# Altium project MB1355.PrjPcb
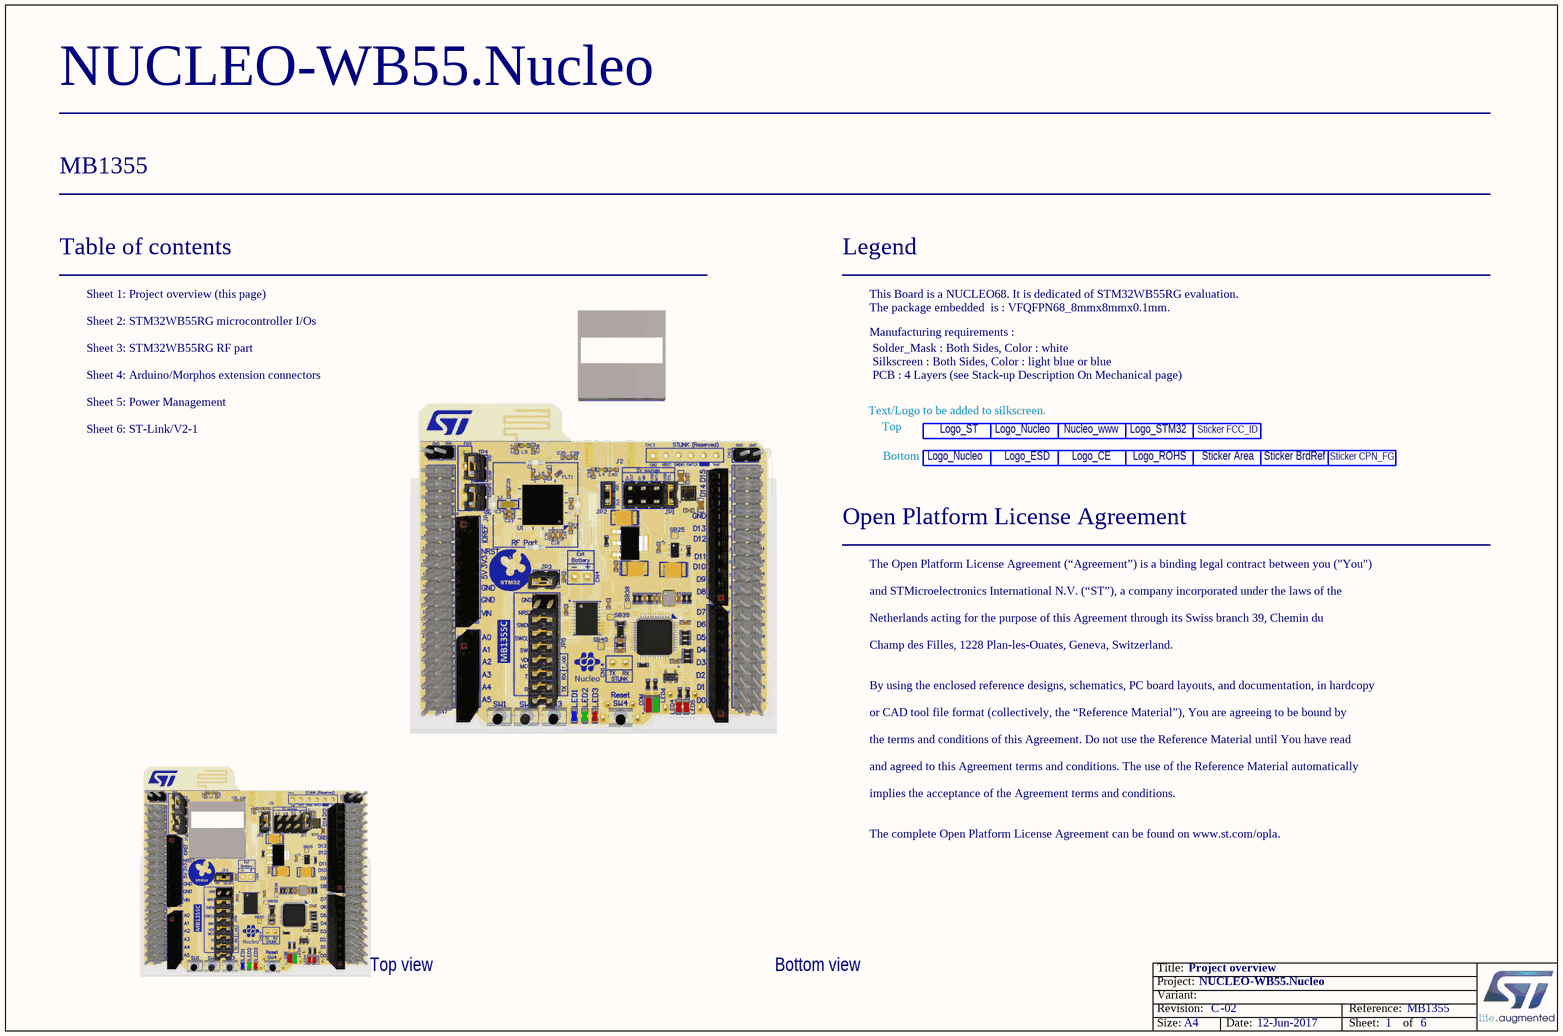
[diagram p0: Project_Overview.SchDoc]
Board_Reference: MB1355; Board_PCB_Revision: C; Board_Name: NUCLEO-WB55.Nucleo; Board_Document_Date: 12-Jun-2017; Board_Assembly_Revision: 02
6 sheets, 214 parts. Net scope: flat (ports and power ports of the same name join across sheets).
Board file: MB1355.PcbDoc
Sheets:
  Project_Overview.SchDoc
  MCU.SchDoc
  RF.SchDoc
  Extension_CN.SchDoc
  ST_LINK_V2-1.SCHDOC
  Power_Management.SchDoc

## Sheet Project_Overview.SchDoc: Project overview
size A4; Date: Not used; ApprovedBy: Not used; CheckedBy: Not used; Author: Ph.A; CompanyName: STMicroelectronics; DrawnBy: Not used; Engineer: Not used; Organization: Not used; Address1: Not used; Address2: Not used; Address3: Not used; Address4: Not used; DocumentNumber: Not used; Revision: Not used; SheetNumber: 1; SheetTotal: 6

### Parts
Label_1  LOGO_ST  [LOGO_ST_Size3]  (value not drawn)
Label_2  LOGO_ROHS  [SYMBOL_RoHS]  (value not drawn)
Label_3  LOGO_Nucleo_www  [LOGO_Nucleo_www]  (value not drawn)
Label_4  LOGO_STM32  [LOGO_STM32]  (value not drawn)
Label_5  LOGO_Nucleo  [LOGO_Nucleo]  (value not drawn)
Label_6  LOGO_CE  [LOGO CE]  (value not drawn)
Label_7  LOGO_ESD  [LOGO ESD]  (value not drawn)
Label_8  LOGO_StickerArea_W21x6  [LOGO_StickerArea_Border]  (value not drawn)
Label_9  LOGO_Nucleo  [LOGO_Nucleo]  (value not drawn)
STICKER_1  FCC_ID_Sticker_16x5  [Sticker_FCC_ID 16x5mm]  (value not drawn)
STICKER_2  Sticker_BrdRef_21x5  [Sticker_BrdRef_21x5mm]  (value not drawn)
STICKER_3  Sticker_CPN_FG 16x5  [Sticker_CPN_FG 16x5mm]  (value not drawn)

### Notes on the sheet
- Table of contents
- Sheet 1: Project overview (this page)
- Legend
- This Board is a NUCLEO68. It is dedicated of STM32WB55RG evaluation.
- The package embedded  is : VFQFPN68_8mmx8mmx0.1mm.
- Sheet 2: STM32WB55RG microcontroller I/Os
- Sheet 3: STM32WB55RG RF part
- Sheet 4: Arduino/Morphos extension connectors
- Manufacturing requirements :
- Silkscreen : Both Sides, Color : light blue or blue
- Solder_Mask : Both Sides, Color : white
- PCB : 4 Layers (see Stack-up Description On Mechanical page)
- Sheet 6: ST-Link/V2-1
- Sheet 5: Power Management
- Text/Logo to be added to silkscreen.
- Top
- Bottom
- Open Platform License Agreement
- The Open Platform License Agreement (“Agreement”) is a binding legal contract between you ("You")
- and STMicroelectronics International N.V. (“ST”), a company incorporated under the laws of the
- Netherlands acting for the purpose of this Agreement through its Swiss branch 39, Chemin du
- Champ des Filles, 1228 Plan-les-Ouates, Geneva, Switzerland.
- By using the enclosed reference designs, schematics, PC board layouts, and documentation, in hardcopy
- or CAD tool file format (collectively, the “Reference Material”), You are agreeing to be bound by
- the terms and conditions of this Agreement. Do not use the Reference Material until You have read
- and agreed to this Agreement terms and conditions. The use of the Reference Material automatically
- implies the acceptance of the Agreement terms and conditions.
- The complete Open Platform License Agreement can be found on www.st.com/opla.
- Top view
- Bottom view

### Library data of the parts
Label_1 = LOGO_ST: Silkscreen Only: YES
Label_2 = LOGO_ROHS: Silkscreen Only: YES
Label_4 = LOGO_STM32: Silkscreen Only: YES
Label_5 Label_9 = LOGO_Nucleo: Silkscreen Only: YES
Label_6 = LOGO_CE: Silkscreen Only: YES
Label_7 = LOGO_ESD: Silkscreen Only: YES
Label_8 = LOGO_StickerArea_W21x6: Silkscreen Only: YES
STICKER_1 = LOGO_Sticker_FCC_ID: Sticker for FCC_ID 16x5mm
STICKER_2 = LOGO_Sticker_BrdRef: Sticker_BrdRef 21x5mm
STICKER_3 = LOGO_Sticker_CPN_FG: Sticker for CPN_FG 16x5mm

## Sheet MCU.SchDoc: STM32WB55RG microcontroller I/Os
size A4; Author: Ph.A; SheetNumber: 2; SheetTotal: 6
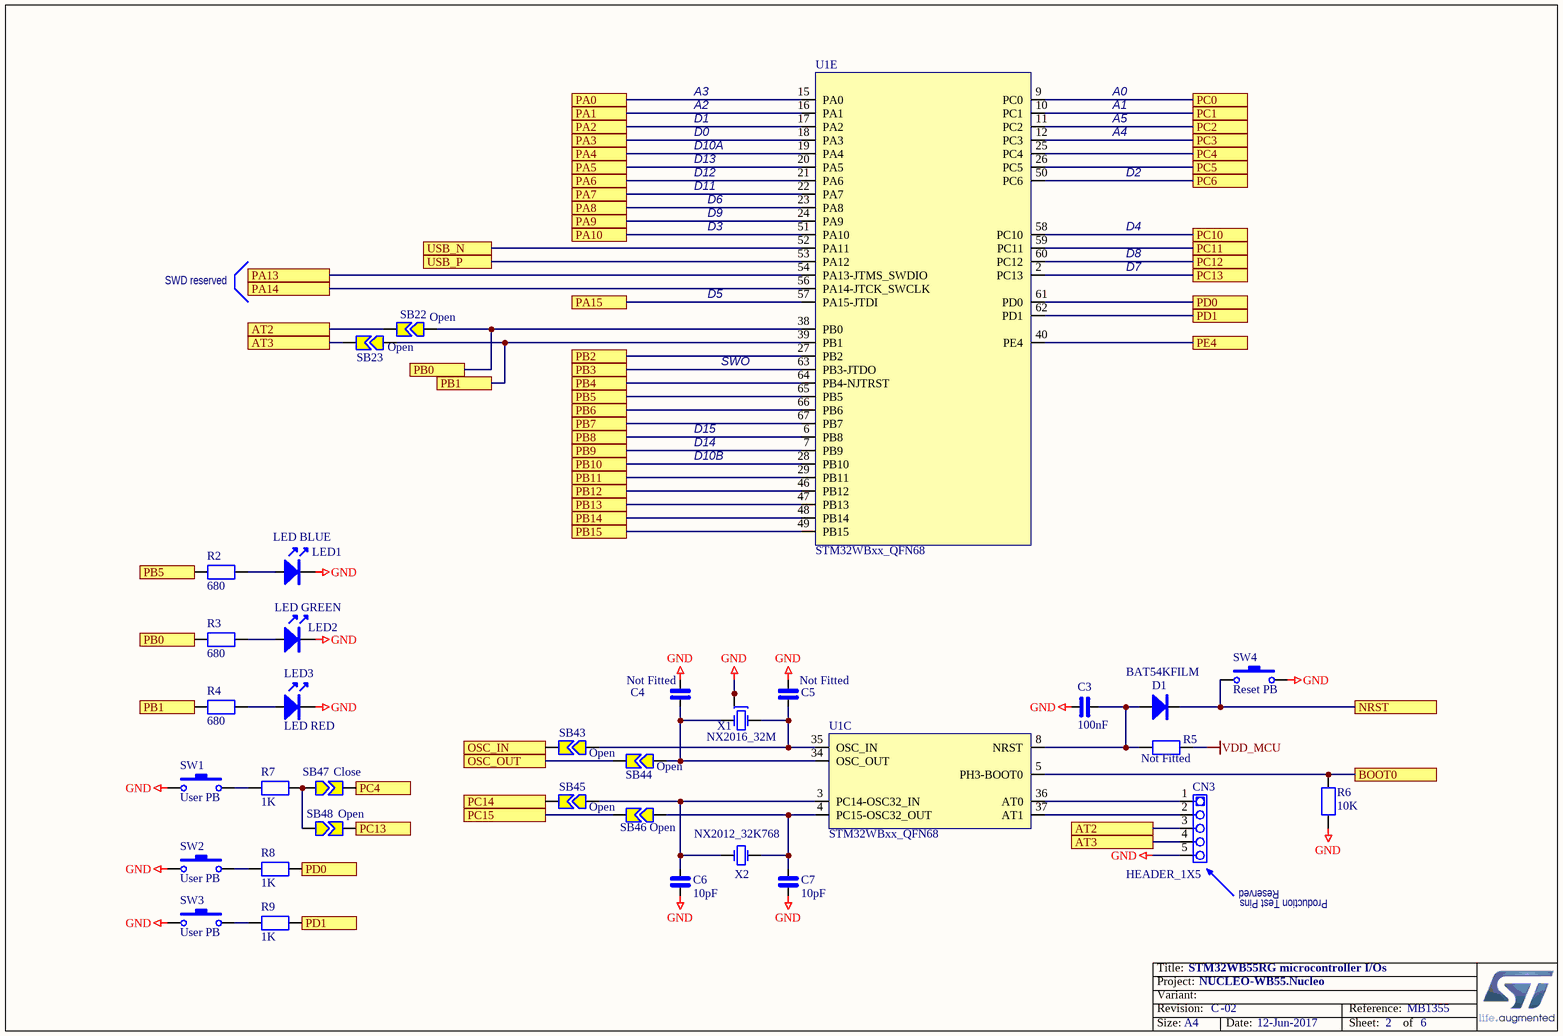
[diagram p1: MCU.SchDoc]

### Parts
C3  100nF  [0402_CAP_NPOL]
C4  Fitted: Not Fitted  [0402_CAP_NPOL]  (hidden comment: TBD)
C5  Fitted: Not Fitted  [0402_CAP_NPOL]  (hidden comment: TBD)
C6  10pF  [0402_CAP_NPOL]
C7  10pF  [0402_CAP_NPOL]
CN3  HEADER_1X5  [Header NF 1x5x2.54 TH]
D1  BAT54KFILM  [SOD523]
LED1  LED BLUE  [0603_LED_Blue]
LED2  LED GREEN  [0603_LED_GREEN]
LED3  LED RED  [0603_LED_RED]
R2  680  [0402_RES]
R3  680  [0402_RES]
R4  680  [0402_RES]
R5  Fitted: Not Fitted  [0402_RES]  (hidden comment: 100K (not fitted))
R6  10K  [0402_RES]
R7  1K  [0402_RES]
R8  1K  [0402_RES]
R9  1K  [0402_RES]
SB22  Open  [SB-tiny]
SB23  Open  [SB-tiny]
SB43  Open  [SB-tiny]
SB44  Open  [SB-tiny]
SB45  Open  [SB-tiny]
SB46  Open  [SB-tiny]
SB47  Close  [SB-tiny]
SB48  Open  [SB-tiny]
SW1  User PB  [SW-PB SMD KMR2]
SW2  User PB  [SW-PB SMD KMR2]
SW3  User PB  [SW-PB SMD KMR2]
SW4  Reset PB  [SW-PB SMD KMR2]
U1  STM32WBxx_QFN68  [VFQFPN68_8x8x0.1_p0.4]  (parts C,E of 5)
X1  NX2016_32M  [NX2016_4P]
X2  NX2012_32K768  [NX2012_2P]

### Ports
AT2, AT3, BOOT0, NRST, OSC_IN, OSC_OUT, PA0, PA1, PA2, PA3, PA4, PA5, PA6, PA7, PA8, PA9, PA10, PA13, PA14, PA15, PB0, PB1, PB2, PB3, PB4, PB5, PB6, PB7, PB8, PB9, PB10, PB11, PB12, PB13, PB14, PB15, PC0, PC1, PC2, PC3, PC4, PC5, PC6, PC10, PC11, PC12, PC13, PC14, PC15, PD0, PD1, PE4, USB_N, USB_P

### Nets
GND: C3.1 C4.2 C5.2 C6.2 C7.2 CN3.5 LED1.K LED2.K LED3.K R6.2 SW1.1 SW2.1 SW3.1 SW4.2 X1.2 X1.4
VDD_MCU: R5.1
AT2: CN3.3 SB22.2 ; port AT2
AT3: CN3.4 SB23.2 ; port AT3
BOOT0: R6.1 U1.5(PH3-BOOT0) ; port BOOT0
NRST: D1.K SW4.1 ; port NRST
OSC_IN: SB43.2 ; port OSC_IN
OSC_OUT: SB44.2 ; port OSC_OUT
PA0: U1.15(PA0) ; port PA0
PA1: U1.16(PA1) ; port PA1
PA2: U1.17(PA2) ; port PA2
PA3: U1.18(PA3) ; port PA3
PA4: U1.19(PA4) ; port PA4
PA5: U1.20(PA5) ; port PA5
PA6: U1.21(PA6) ; port PA6
PA7: U1.22(PA7) ; port PA7
PA8: U1.23(PA8) ; port PA8
PA9: U1.24(PA9) ; port PA9
PA10: U1.51(PA10) ; port PA10
PA13: U1.54(PA13-JTMS_SWDIO) ; port PA13
PA14: U1.56(PA14-JTCK_SWCLK) ; port PA14
PA15: U1.57(PA15-JTDI) ; port PA15
PB0: R3.1 SB22.1 U1.38(PB0) ; port PB0
PB1: R4.1 SB23.1 U1.39(PB1) ; port PB1
PB2: U1.27(PB2) ; port PB2
PB3: U1.63(PB3-JTDO) ; port PB3
PB4: U1.64(PB4-NJTRST) ; port PB4
PB5: R2.1 U1.65(PB5) ; port PB5
PB6: U1.66(PB6) ; port PB6
PB7: U1.67(PB7) ; port PB7
PB8: U1.6(PB8) ; port PB8
PB9: U1.7(PB9) ; port PB9
PB10: U1.28(PB10) ; port PB10
PB11: U1.29(PB11) ; port PB11
PB12: U1.46(PB12) ; port PB12
PB13: U1.47(PB13) ; port PB13
PB14: U1.48(PB14) ; port PB14
PB15: U1.49(PB15) ; port PB15
PC0: U1.9(PC0) ; port PC0
PC1: U1.10(PC1) ; port PC1
PC2: U1.11(PC2) ; port PC2
PC3: U1.12(PC3) ; port PC3
PC4: SB47.2 U1.25(PC4) ; port PC4
PC5: U1.26(PC5) ; port PC5
PC6: U1.50(PC6) ; port PC6
PC10: U1.58(PC10) ; port PC10
PC11: U1.59(PC11) ; port PC11
PC12: U1.60(PC12) ; port PC12
PC13: SB48.2 U1.2(PC13) ; port PC13
PC14: SB45.2 ; port PC14
PC15: SB46.2 ; port PC15
PD0: R8.2 U1.61(PD0) ; port PD0
PD1: R9.2 U1.62(PD1) ; port PD1
PE4: U1.40(PE4) ; port PE4
USB_N: U1.52(PA11) ; port USB_N
USB_P: U1.53(PA12) ; port USB_P
NetC3_2: C3.2 D1.A R5.2 U1.8(NRST)
NetC4_1: C4.1 SB44.1 U1.34(OSC_OUT) X1.3(OSC2)
NetC5_1: C5.1 SB43.1 U1.35(OSC_IN) X1.1(OSC1)
NetC6_1: C6.1 SB45.1 U1.3(PC14-OSC32_IN) X2.1(OSC1)
NetC7_1: C7.1 SB46.1 U1.4(PC15-OSC32_OUT) X2.2(OSC2)
NetCN3_1: CN3.1 U1.36(AT0)
NetCN3_2: CN3.2 U1.37(AT1)
NetLED1_A: LED1.A R2.2
NetLED2_A: LED2.A R3.2
NetLED3_A: LED3.A R4.2
NetR7_1: R7.1 SW1.2
NetR7_2: R7.2 SB47.1 SB48.1
NetR8_1: R8.1 SW2.2
NetR9_1: R9.1 SW3.2

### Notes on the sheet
- A2
- A3
- A0
- A1
- D12
- D13
- D0
- D1
- D10A
- A4
- A5
- D2
- D11
- D9
- D3
- D6
- D4
- SWD reserved
- D5
- D7
- D8
- SWO
- D14
- D15
- D10B
- (near CN3) Reserved
- (near CN3) Production Test Pins

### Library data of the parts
C3-C7 = CAP_NPOL: Capacitor_not polarized
D1 = BAT54K: Schottky Diode
LED1-LED3 = LED: Light-Emitting Diode
R2-R9 = RES: Resistor
SB22 SB23 SB43-SB48 = Strap2: Solder Jumper; Solder: YES
SW1-SW4 = SW-PB_1: Push-button SMD; Order code RS: 102-412
X1 = NX2016_32M: Crystal NDK 2.0x1.6mm  32 MHz; Manufacturer P/N: NX2016SA 32 MHz EXS00A-CS06654; Ref: NX2016SA 32MHz  EXS00A-CS06654  Référence interne NDK : X5087283
X2 = NX2012_32K768: Crystal NDK 2.0x1.2mm  32.768 KHz; Manufacturer P/N: NX2012SA 32.768KHz  EXS00A-MU00389; Ref: NX2012SA 32.768KHz  EXS00A-MU00389  Référence interne NDK : X3037088

## Sheet RF.SchDoc: STM32WB55RG RF part
size A4; Author: PhA; SheetNumber: 3; SheetTotal: 6
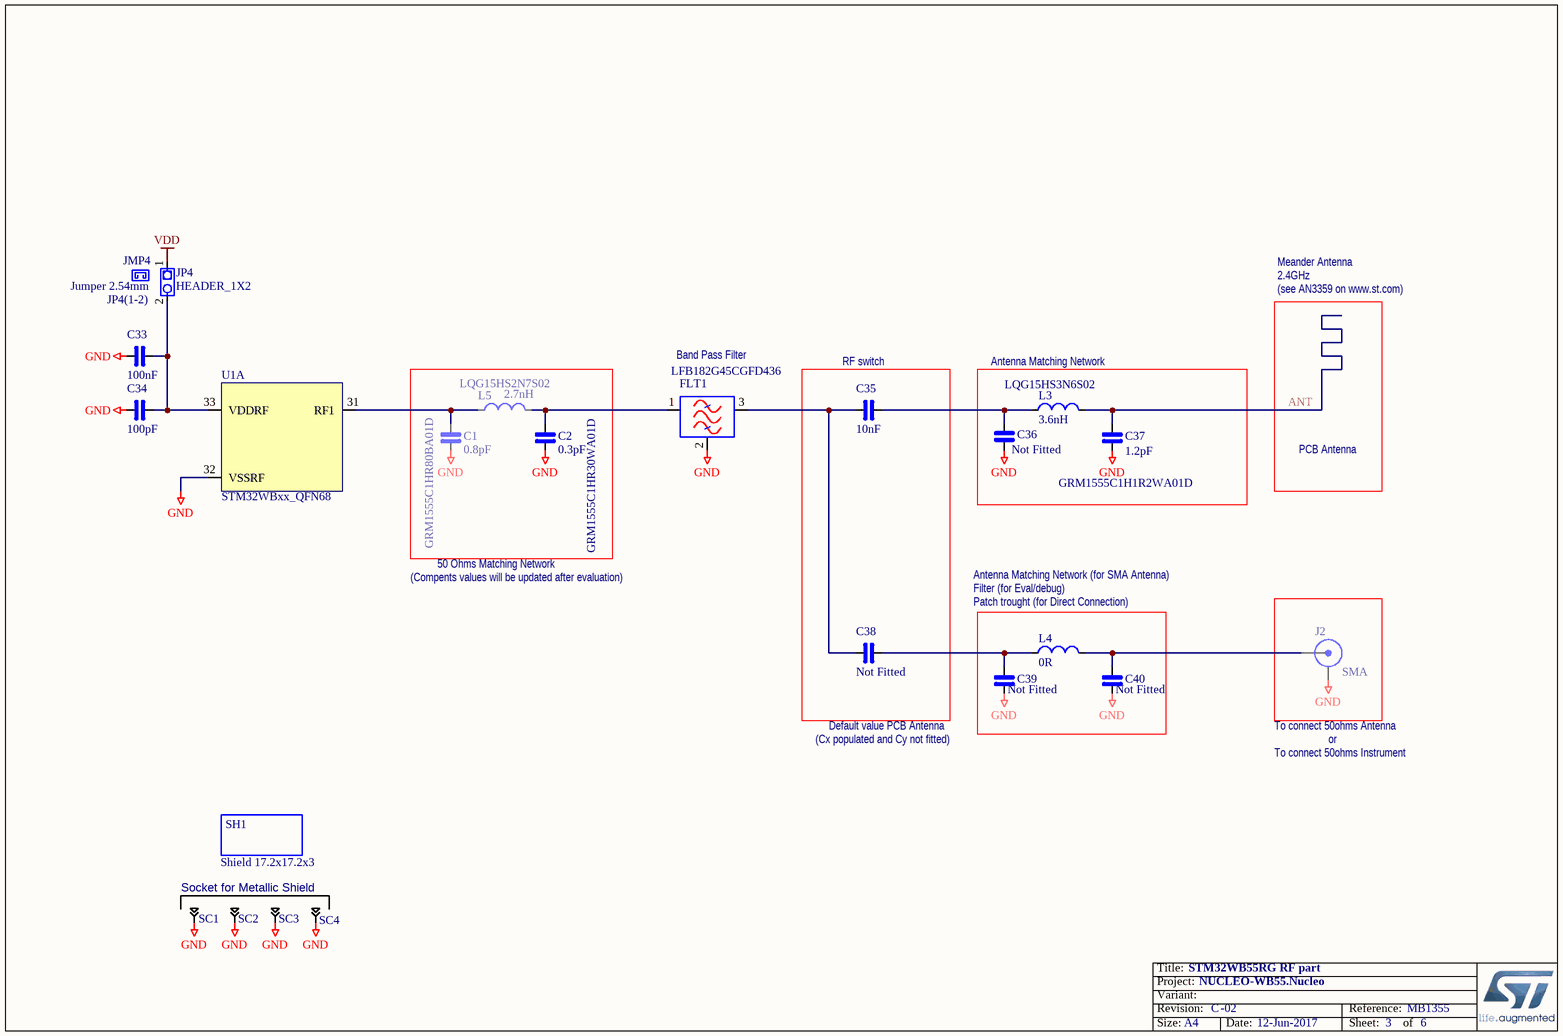
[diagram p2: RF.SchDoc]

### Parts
C1  0.8pF  REF: GRM1555C1HR80BA01D  [0402_CAP_NPOL]
C2  0.3pF  REF: GRM1555C1HR30WA01D  [0402_CAP_NPOL]
C33  100nF  [0402_CAP_NPOL]
C34  100pF  [0402_CAP_NPOL]
C35  10nF  [0402_CAP_NPOL]
C36  Fitted: Not Fitted  [0402_CAP_NPOL]
C37  1.2pF  Ref: GRM1555C1H1R2WA01D  [0402_CAP_NPOL]
C38  Fitted: Not Fitted  [0402_CAP_NPOL]
C39  Fitted: Not Fitted  [0402_CAP_NPOL]
C40  Fitted: Not Fitted  [0402_CAP_NPOL]
FLT1  LFB182G45CGFD436  [LFB182G45CGFD436]
J2  SMA  [SMA_T_9.52_NF]
JMP4  Jumper 2.54mm  default: JP4(1-2)  [Jumper 2.54mm BLACK]
JP4  HEADER_1X2  [Header M 1x2x2.54 TH V]
L3  3.6nH  Ref: LQG15HS3N6S02  [0402_COIL]
L4  0R  [0402_COIL]
L5  2.7nH  Ref: LQG15HS2N7S02  [0402_COIL]
SC1  Shield Clip_A 3.9x1.1x1.28  [Shield Clip_A 3.9x1.1x1.28]  (value not drawn)
SC2  Shield Clip_A 3.9x1.1x1.28  [Shield Clip_A 3.9x1.1x1.28]  (value not drawn)
SC3  Shield Clip_A 3.9x1.1x1.28  [Shield Clip_A 3.9x1.1x1.28]  (value not drawn)
SC4  Shield Clip_A 3.9x1.1x1.28  [Shield Clip_A 3.9x1.1x1.28]  (value not drawn)
SH1  Shield 17.2x17.2x3  [Shield 17.2x17.2x3]
U1  STM32WBxx_QFN68  [VFQFPN68_8x8x0.1_p0.4]  (part A of 5)

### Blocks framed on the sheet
RF switch: C35 C38
Antenna Matching Network: C36 C37 L3

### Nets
GND: C1.1 C2.1 C33.1 C34.1 C36.2 C37.1 C39.1 C40.1 FLT1.2(GND) J2.2(Y) SC1.1 SC2.1 SC3.1 SC4.1 U1.32(VSSRF)
VDD: JP4.1
ANT: C37.2 L3.2
NetC1_2: C1.2 L5.1 U1.31(RF1)
NetC2_2: C2.2 FLT1.1(I/O) L5.2
NetC33_2: C33.2 C34.2 JP4.2 U1.33(VDDRF)
NetC35_1: C35.1 C38.1 FLT1.3(I/O)
NetC35_2: C35.2 C36.1 L3.1
NetC38_2: C38.2 C39.2 L4.1
NetC40_2: C40.2 J2.1(X) L4.2

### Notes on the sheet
- Meander Antenna
- 2.4GHz
- (see AN3359 on www.st.com)
- (near FLT1) Band Pass Filter
- PCB Antenna
- (Compents values will be updated after evaluation)
- 50 Ohms Matching Network
- Antenna Matching Network (for SMA Antenna)
- Filter (for Eval/debug)
- Patch trought (for Direct Connection)
- (near C39) (Cx populated and Cy not fitted)
- Default value PCB Antenna
- To connect 50ohms Antenna
- To connect 50ohms Instrument
- or
- Socket for Metallic Shield

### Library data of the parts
C1 C2 C33 C34 C36-C40 = CAP_NPOL: Capacitor_not polarized
C35 = CAP_NPOL: Capacitor_not polarized; Ref: Murata GRM155R71H103KA88
FLT1 = LFB182G45CGFD436: Band Pass Filter Murata LFB182G45CGFD436
JP4 = HEADER_1X2_L
L3-L5 = INDUCTOR_SMD_STDL
SC1-SC4 = Shield Clip_A 3.9x1.1x1.28: Harwin S0951-46R
SH1 = Shield

## Sheet Extension_CN.SchDoc: Arduino/Morphos extension connectors
size A4; Author: Ph.A; SheetNumber: 4; SheetTotal: 6
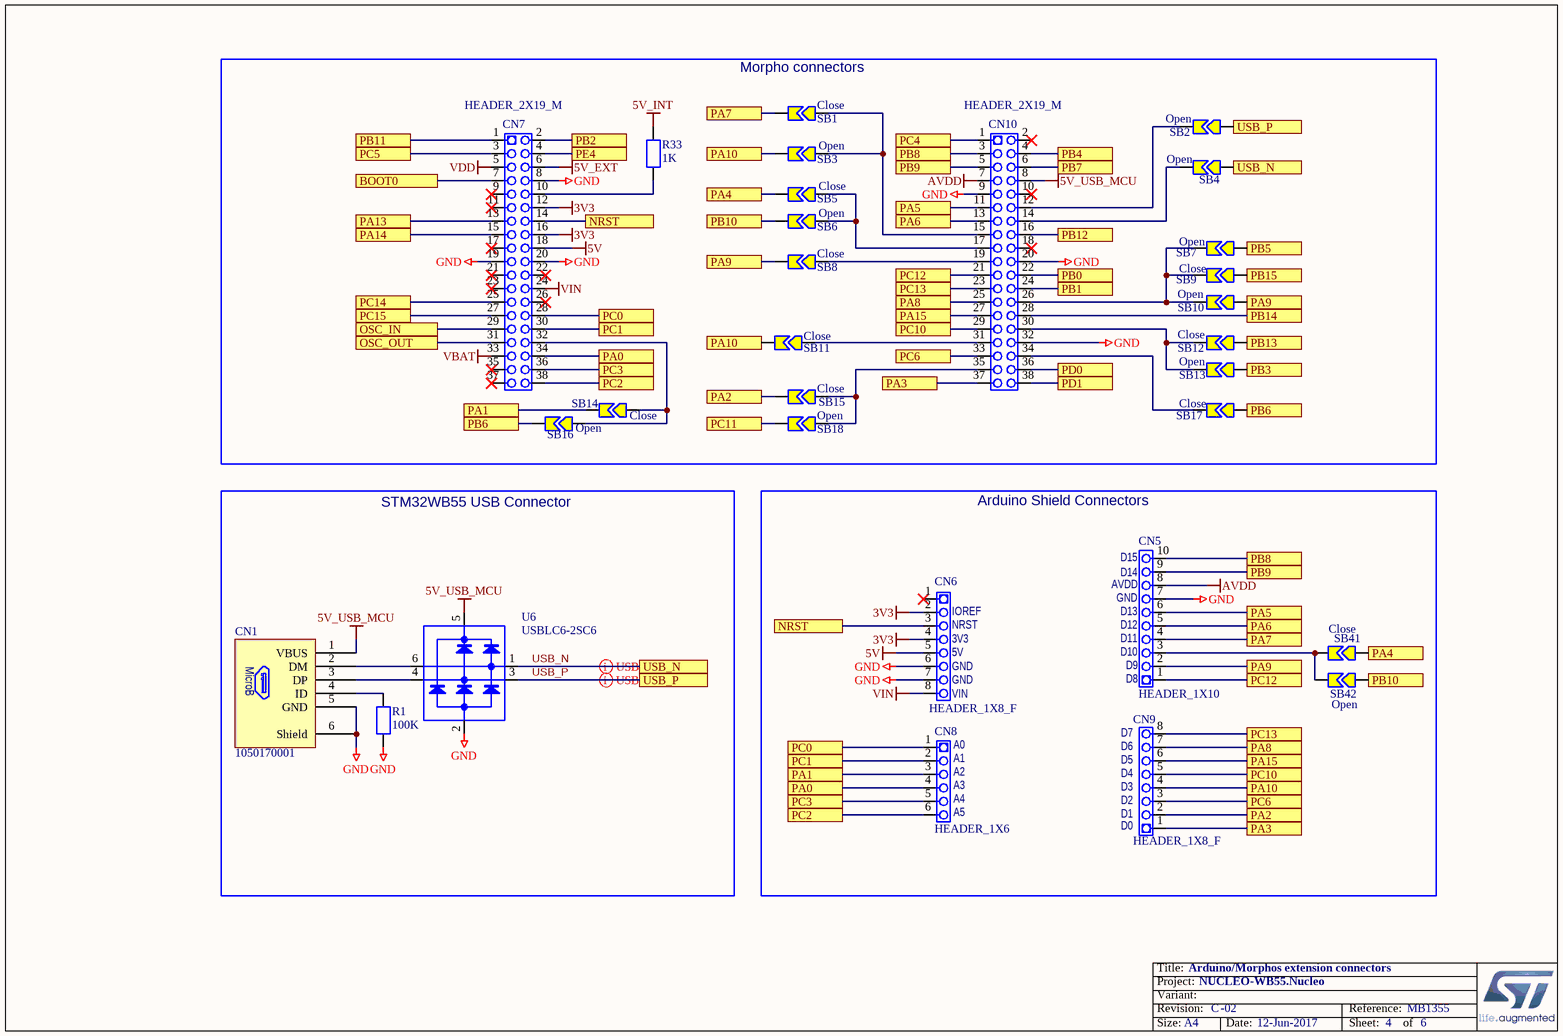
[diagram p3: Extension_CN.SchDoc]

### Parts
CN1  1050170001  [USBMICROB_MOLEX_105017-0001_H2P90]
CN5  HEADER_1X10  [Header F 1x10x2.54 TH V]
CN6  HEADER_1X8_F  [Header F 1x8x2.54 TH V]
CN7  HEADER_2X19_M  [Header M 2x19x2.54 TH M_top + M_bottom]
CN8  HEADER_1X6  [Header F 1x6x2.54 TH V]
CN9  HEADER_1X8_F  [Header F 1x8x2.54 TH V]
CN10  HEADER_2X19_M  [Header M 2x19x2.54 TH M_top + M_bottom]
R1  100K  [0402_RES]
R33  1K  [0402_RES]
SB1  Close  [SB-tiny]
SB2  Open  [SB-tiny]
SB3  Open  [SB-tiny]
SB4  Open  [SB-tiny]
SB5  Close  [SB-tiny]
SB6  Open  [SB-tiny]
SB7  Open  [SB-tiny]
SB8  Close  [SB-tiny]
SB9  Close  [SB-tiny]
SB10  Open  [SB-tiny]
SB11  Close  [SB-tiny]
SB12  Close  [SB-tiny]
SB13  Open  [SB-tiny]
SB14  Close  [SB-tiny]
SB15  Close  [SB-tiny]
SB16  Open  [SB-tiny]
SB17  Close  [SB-tiny]
SB18  Open  [SB-tiny]
SB41  Close  [SB-tiny]
SB42  Open  [SB-tiny]
U6  USBLC6-2SC6  [SOT23-6]

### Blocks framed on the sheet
Morpho connectors: CN7 CN10 R33 SB1-SB18
STM32WB55 USB Connector: CN1 R1 U6
Arduino Shield Connectors: CN5 CN6 CN8 CN9 SB41 SB42

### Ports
BOOT0, NRST, OSC_IN, OSC_OUT, PA0, PA1, PA2, PA3, PA4, PA5, PA6, PA7, PA8, PA9, PA10, PA13, PA14, PA15, PB0, PB1, PB2, PB3, PB4, PB5, PB6, PB7, PB8, PB9, PB10, PB11, PB12, PB13, PB14, PB15, PC0, PC1, PC2, PC3, PC4, PC5, PC6, PC10, PC11, PC12, PC13, PC14, PC15, PD0, PD1, PE4, USB_N, USB_P

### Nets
3V3: CN6.2 CN6.4 CN7.12 CN7.16
5V: CN6.5 CN7.18
5V_EXT: CN7.6
5V_INT: R33.2
5V_USB_MCU: CN1.1(VBUS) CN10.8 U6.5
AVDD: CN5.8 CN10.7
GND: CN1.5(GND) CN1.6(Shield) CN5.7 CN6.6 CN6.7 CN7.8 CN7.19 CN7.20 CN10.9 CN10.20 CN10.32 R1.1 U6.2
VBAT: CN7.33
VDD: CN7.5
VIN: CN6.8 CN7.24
BOOT0: CN7.7 ; port BOOT0
NRST: CN6.3 CN7.14 ; port NRST
OSC_IN: CN7.29 ; port OSC_IN
OSC_OUT: CN7.31 ; port OSC_OUT
PA0: CN7.34 CN8.4 ; port PA0
PA1: CN8.3 SB14.2 ; port PA1
PA2: CN9.2 SB15.2 ; port PA2
PA3: CN9.1 CN10.37 ; port PA3
PA4: SB5.2 SB41.1 ; port PA4
PA5: CN5.6 CN10.11 ; port PA5
PA6: CN5.5 CN10.13 ; port PA6
PA7: CN5.4 SB1.2 ; port PA7
PA8: CN9.7 CN10.25 ; port PA8
PA9: CN5.2 SB8.2 SB10.1 ; port PA9
PA10: CN9.4 SB3.2 SB11.2 ; port PA10
PA13: CN7.13 ; port PA13
PA14: CN7.15 ; port PA14
PA15: CN9.6 CN10.27 ; port PA15
PB0: CN10.22 ; port PB0
PB1: CN10.24 ; port PB1
PB2: CN7.2 ; port PB2
PB3: SB13.1 ; port PB3
PB4: CN10.4 ; port PB4
PB5: SB7.1 ; port PB5
PB6: SB16.2 SB17.1 ; port PB6
PB7: CN10.6 ; port PB7
PB8: CN5.10 CN10.3 ; port PB8
PB9: CN5.9 CN10.5 ; port PB9
PB10: SB6.2 SB42.1 ; port PB10
PB11: CN7.1 ; port PB11
PB12: CN10.16 ; port PB12
PB13: SB12.1 ; port PB13
PB14: CN10.28 ; port PB14
PB15: SB9.1 ; port PB15
PC0: CN7.28 CN8.1 ; port PC0
PC1: CN7.30 CN8.2 ; port PC1
PC2: CN7.38 CN8.6 ; port PC2
PC3: CN7.36 CN8.5 ; port PC3
PC4: CN10.1 ; port PC4
PC5: CN7.3 ; port PC5
PC6: CN9.3 CN10.33 ; port PC6
PC10: CN9.5 CN10.29 ; port PC10
PC11: SB18.2 ; port PC11
PC12: CN5.1 CN10.21 ; port PC12
PC13: CN9.8 CN10.23 ; port PC13
PC14: CN7.25 ; port PC14
PC15: CN7.27 ; port PC15
PD0: CN10.36 ; port PD0
PD1: CN10.38 ; port PD1
PE4: CN7.4 ; port PE4
USB_N: SB4.1 U6.1 ; port USB_N
USB_P: SB2.1 U6.3 ; port USB_P
NetCN1_2: CN1.2(DM) U6.6
NetCN1_3: CN1.3(DP) U6.4
NetCN1_4: CN1.4(ID) R1.2
NetCN5_3: CN5.3 SB41.2 SB42.2
NetCN7_10: CN7.10 R33.1
NetCN7_32: CN7.32 SB14.1 SB16.1
NetCN10_12: CN10.12 SB2.2
NetCN10_14: CN10.14 SB4.2
NetCN10_15: CN10.15 SB1.1 SB3.1
NetCN10_17: CN10.17 SB5.1 SB6.1
NetCN10_19: CN10.19 SB8.1
NetCN10_26: CN10.26 SB7.2 SB9.2 SB10.2
NetCN10_30: CN10.30 SB12.2 SB13.2
NetCN10_31: CN10.31 SB11.1
NetCN10_34: CN10.34 SB17.2
NetCN10_35: CN10.35 SB15.1 SB18.1

Not connected (* = marked no-connect by the designer): CN6 1*; CN7 9* 11* 17* 21* 22* 23* 26* 35* 37*; CN10 2* 10* 18*

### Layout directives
differential pair; net class DIFF90: USB_N, USB_P

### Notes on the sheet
- (near CN5) D14
- (near CN5) D15
- (near CN6) 3V3
- (near CN6) NRST
- (near CN6) IOREF
- (near CN5) AVDD
- (near CN5) GND
- (near CN5) D10
- (near CN5) D11
- (near CN5) D12
- (near CN5) D13
- (near CN6) GND
- (near CN6) VIN
- (near CN6) 5V
- (near CN5) D9
- (near CN5) D8
- (near CN8) A0
- (near CN8) A1
- (near CN8) A2
- (near CN8) A3
- (near CN9) D3
- (near CN9) D4
- (near CN9) D5
- (near CN9) D6
- (near CN9) D7
- (near CN8) A5
- (near CN8) A4
- (near CN9) D0
- (near CN9) D1
- (near CN9) D2

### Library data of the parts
CN1 = 1050170001: USB-MICRO-B, 1050170001, SMT, MOLEX; Fitted: YES; Ordered_By: Subcon
CN6 = HEADER_1X8: Specific Function: Arduino Power
CN7 = HEADER_2X19: Specific Function: Morpho CN7
CN9 = HEADER_1X8: Specific Function: Arduino Digital 1
CN10 = HEADER_2X19: Specific Function: Morpho CN10
R1 R33 = RES: Resistor
SB1-SB18 SB41 SB42 = Strap2: Solder Jumper; Solder: YES
U6 = USBLC6-2

## Sheet ST_LINK_V2-1.SCHDOC: ST-Link/V2-1
size A4; Author: Ph.A; SheetNumber: 6; SheetTotal: 6
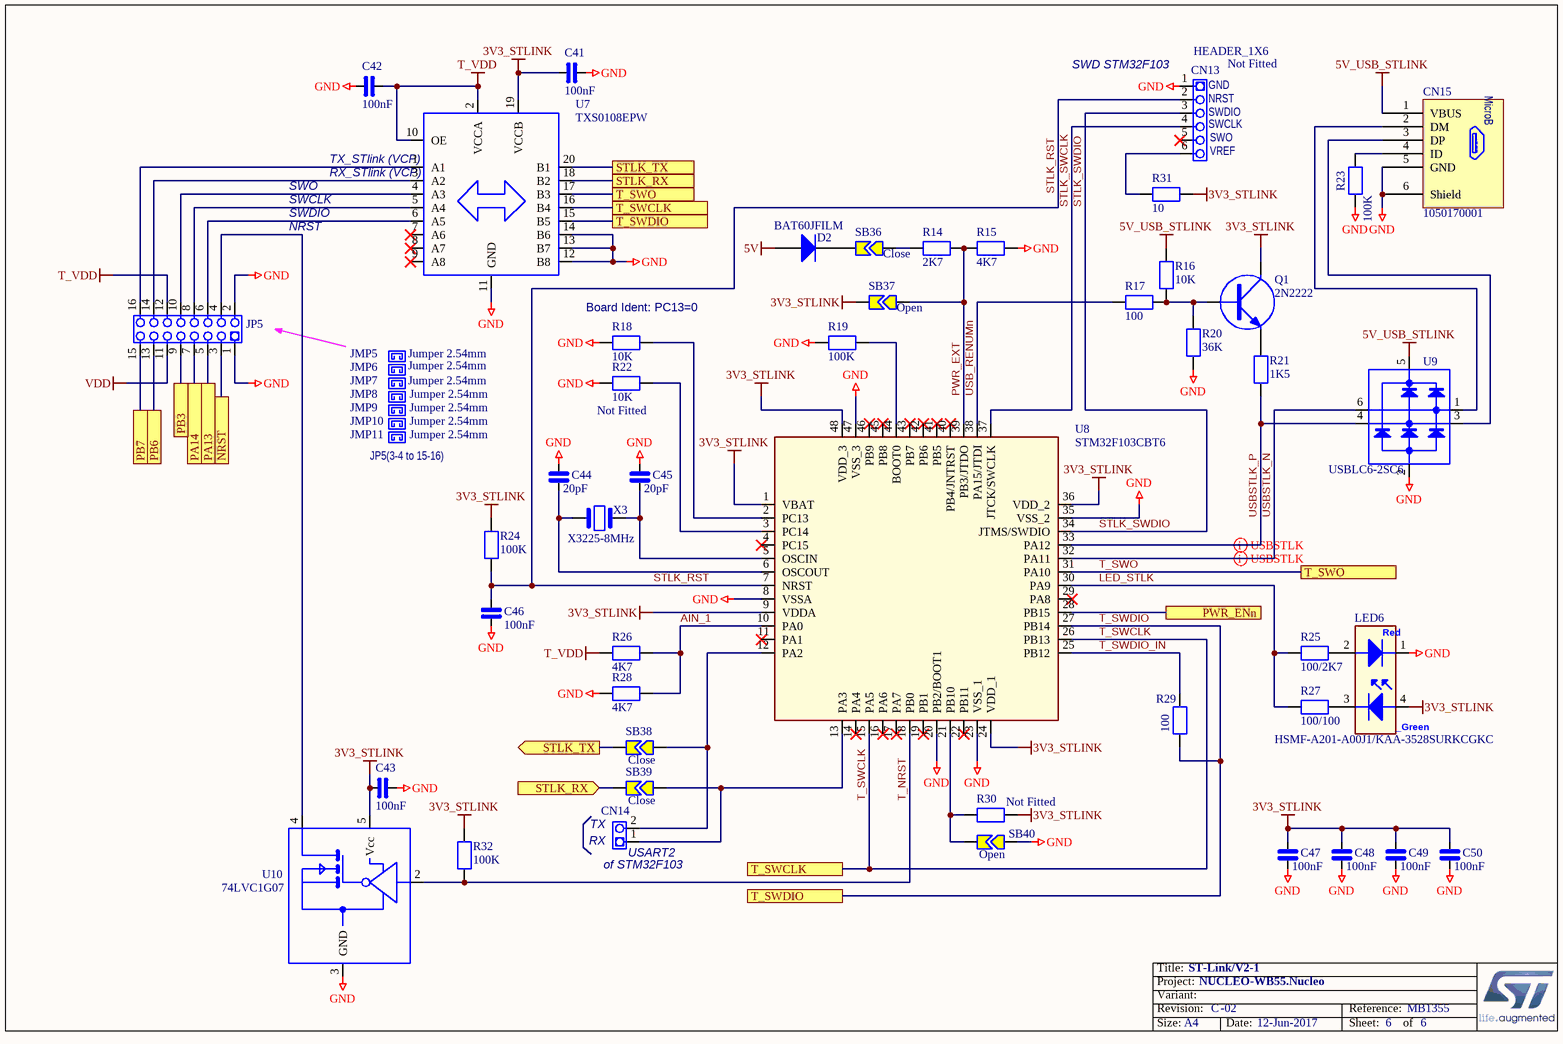
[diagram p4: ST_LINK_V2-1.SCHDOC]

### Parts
C41  100nF  [0402_CAP_NPOL]
C42  100nF  [0402_CAP_NPOL]
C43  100nF  [0402_CAP_NPOL]
C44  20pF  [0402_CAP_NPOL]
C45  20pF  [0402_CAP_NPOL]
C46  100nF  [0402_CAP_NPOL]
C47  100nF  [0402_CAP_NPOL]
C48  100nF  [0402_CAP_NPOL]
C49  100nF  [0402_CAP_NPOL]
C50  100nF  [0402_CAP_NPOL]
CN13  HEADER_1X6  Fitted: Not Fitted  [Header NF 1x6x2.54 TH]
CN14  HEADER_1X2  [Header NF 1x2x2.54 TH]  (value not drawn)
CN15  1050170001  [USBMICROB_MOLEX_105017-0001_H2P90]
D2  BAT60JFILM  [SOD-323]
JMP5  Jumper 2.54mm  [Jumper 2.54mm BLACK]
JMP6  Jumper 2.54mm  [Jumper 2.54mm BLACK]
JMP7  Jumper 2.54mm  [Jumper 2.54mm BLACK]
JMP8  Jumper 2.54mm  [Jumper 2.54mm BLACK]
JMP9  Jumper 2.54mm  [Jumper 2.54mm BLACK]
JMP10  Jumper 2.54mm  [Jumper 2.54mm BLACK]
JMP11  Jumper 2.54mm  [Jumper 2.54mm BLACK]
JP5  HEADER_2X8  [Header M 2x8x2.54 TH V]  (value not drawn)
LED6  HSMF-A201-A00J1/KAA-3528SURKCGKC  [HSMF-A201]
Q1  2N2222  [SOT23-3]
R14  2K7  [0402_RES]
R15  4K7  [0402_RES]
R16  10K  [0402_RES]
R17  100  [0402_RES]
R18  10K  [0402_RES]
R19  100K  [0402_RES]
R20  36K  [0402_RES]
R21  1K5  [0402_RES]
R22  10K  Fitted: Not Fitted  [0402_RES]
R23  100K  [0402_RES]
R24  100K  [0402_RES]
R25  100/2K7  [0402_RES]
R26  4K7  [0402_RES]
R27  100/100  [0402_RES]
R28  4K7  [0402_RES]
R29  100  [0402_RES]
R30  Fitted: Not Fitted  [0402_RES]
R31  10  [0402_RES]
R32  100K  [0402_RES]
SB36  Close  [SB-tiny]
SB37  Open  [SB-tiny]
SB38  Close  [SB-tiny]
SB39  Close  [SB-tiny]
SB40  Open  [SB-tiny]
U7  TXS0108EPW  [TSSOP20]
U8  STM32F103CBT6  [LQFP48_7X7_P050]
U9  USBLC6-2SC6  [SOT23-6]
U10  74LVC1G07  [SOT353-1]
X3  X3225-8MHz  [X3225]

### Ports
NRST, PA13, PA14, PB3, PB6, PB7, PWR_ENn, STLK_RX, STLK_RX (in), STLK_TX, STLK_TX (out), T_SWCLK, T_SWDIO, T_SWO

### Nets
3V3_STLINK: C41.1 C43.1 C47.1 C48.1 C49.1 C50.1 LED6.4 Q1.3(C) R24.2 R30.1 R31.2 R32.2 SB37.1 U7.19(VCCB) U8.1(VBAT) U8.9(VDDA) U8.24(VDD_1) U8.36(VDD_2) U8.48(VDD_3) U10.5(Vcc)
5V: D2.1(A)
5V_USB_STLINK: CN15.1(VBUS) R16.2 U9.5
GND: C41.2 C42.1 C43.2 C44.1 C45.1 C46.1 C47.2 C48.2 C49.2 C50.2 CN13.1 CN15.5(GND) CN15.6(Shield) JP5.1 JP5.2 LED6.1 R15.2 R18.2 R19.1 R20.1 R22.2 R23.1 R28.2 SB40.2 U7.11(GND) U7.12(B8) U7.13(B7) U7.14(B6) U8.8(VSSA) U8.20(PB2/BOOT1) U8.23(VSS_1) U8.35(VSS_2) U8.47(VSS_3) U9.2 U10.3(GND)
T_VDD: C42.2 JP5.12 R26.2 U7.2(VCCA) U7.10(OE)
VDD: JP5.11
AIN_1: R26.1 R28.1 U8.10(PA0)
LED_STLK: R25.2 R27.2 U8.30(PA9)
NRST: JP5.3 ; port NRST
PA13: JP5.5 ; port PA13
PA14: JP5.7 ; port PA14
PB3: JP5.9 ; port PB3
PB6: JP5.13 ; port PB6
PB7: JP5.15 ; port PB7
PWR_ENn: U8.28(PB15) ; port PWR_ENn
PWR_EXT: R14.2 R15.1 SB37.2 U8.39(PB3/JTDO)
STLK_RST: C46.2 CN13.2 R24.1 U8.7(NRST)
STLK_RX: SB39.1 U7.18(B2) ; port STLK_RX
STLK_SWCLK: CN13.4 U8.37(JTCK/SWCLK)
STLK_SWDIO: CN13.3 U8.34(JTMS/SWDIO)
STLK_TX: SB38.1 U7.20(B1) ; port STLK_TX
T_NRST: R32.1 U8.18(PB0) U10.2(A)
T_SWCLK: U7.16(B4) U8.15(PA5) U8.26(PB13) ; port T_SWCLK
T_SWDIO: R29.1 U7.15(B5) U8.27(PB14) ; port T_SWDIO
T_SWDIO_IN: R29.2 U8.25(PB12)
T_SWO: U7.17(B3) U8.31(PA10) ; port T_SWO
USB_RENUMn: R17.2 U8.38(PA15/JTDI)
USBSTLK_N: U8.32(PA11) U9.6
USBSTLK_P: R21.1 U8.33(PA12) U9.4
NetC44_2: C44.2 U8.6(OSCOUT) X3.1
NetC45_2: C45.2 U8.5(OSCIN) X3.3
NetCN13_6: CN13.6 R31.1
NetCN14_1: CN14.1 SB39.2 U8.13(PA3)
NetCN14_2: CN14.2 SB38.2 U8.12(PA2)
NetCN15_2: CN15.2(DM) U9.1
NetCN15_3: CN15.3(DP) U9.3
NetCN15_4: CN15.4(ID) R23.2
NetD2_2: D2.2(K) SB36.1
NetJP5_4: JP5.4 U10.4(Y)
NetJP5_6: JP5.6 U7.6(A5)
NetJP5_8: JP5.8 U7.5(A4)
NetJP5_10: JP5.10 U7.4(A3)
NetJP5_14: JP5.14 U7.3(A2)
NetJP5_16: JP5.16 U7.1(A1)
NetLED6_2: LED6.2 R25.1
NetLED6_3: LED6.3 R27.1
NetQ1_1: Q1.1(B) R16.1 R17.1 R20.2
NetQ1_2: Q1.2(E) R21.2
NetR14_1: R14.1 SB36.2
NetR18_1: R18.1 U8.2(PC13)
NetR19_2: R19.2 U8.44(BOOT0)
NetR22_1: R22.1 U8.3(PC14)
NetR30_2: R30.2 SB40.1 U8.21(PB10)

Not connected (* = marked no-connect by the designer): CN13 5*; U7 7(A6)* 8(A7)* 9(A8)*; U8 4(PC15)* 11(PA1)* 14(PA4)* 16(PA6)* 17(PA7)* 19(PB1)* 22(PB11)* 29(PA8)* 40(PB4/JNTRST)* 41(PB5)* 42(PB6)* 43(PB7)* 45(PB8)* 46(PB9)*

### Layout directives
differential pair; net class DIFF90: USBSTLK_N, USBSTLK_P

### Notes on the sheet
- (near CN13) SWD STM32F103
- (near CN13) SWDIO
- (near CN13) NRST
- (near CN13) GND
- TX_STlink (VCP)
- RX_STlink (VCP)
- (near CN13) SWCLK
- (near CN13) SWO
- (near CN13) VREF
- SWO
- SWCLK
- SWDIO
- NRST
- Board Ident: PC13=0
- (near JMP11) JP5(3-4 to 15-16)
- (near CN14) RX
- TX
- (near CN14) USART2
- (near CN14) of STM32F103

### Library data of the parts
C41-C50 = CAP_NPOL: Capacitor_not polarized
CN15 = 1050170001: as CN1 on sheet Extension_CN
D2 = Diode: Default Diode; Code - JEDEC: DO-214-AB; Ordered by: STM; ECCN_US/EU: EAR99/NEC
LED6 = LD_BICOLOR_CMS: Bicolor Led; Manuf_1: Avago Technologies; Manuf_2: kingbright
Q1 = 2N2222: 2N2222_SOT23
R14-R32 = RES: Resistor
SB36-SB40 = Strap2: Solder Jumper; Solder: YES
U7 = TXS0108EPW: TXS0108E Bi-directional Level Shifter TSSOP20
U8 = STM32F103CBT6: Medium-density performance line ARM-based 32-bit MCU with 128KB Flash; Manuf_1: STM; ECCN_US/EU: 3A991A2/NEC; Fitted: YES
U9 = USBLC6-2
X3 = X3225: Crystal 8MHz

## Sheet Power_Management.SchDoc: Power Management
size A4; Author: Ph.A; SheetNumber: 5; SheetTotal: 6
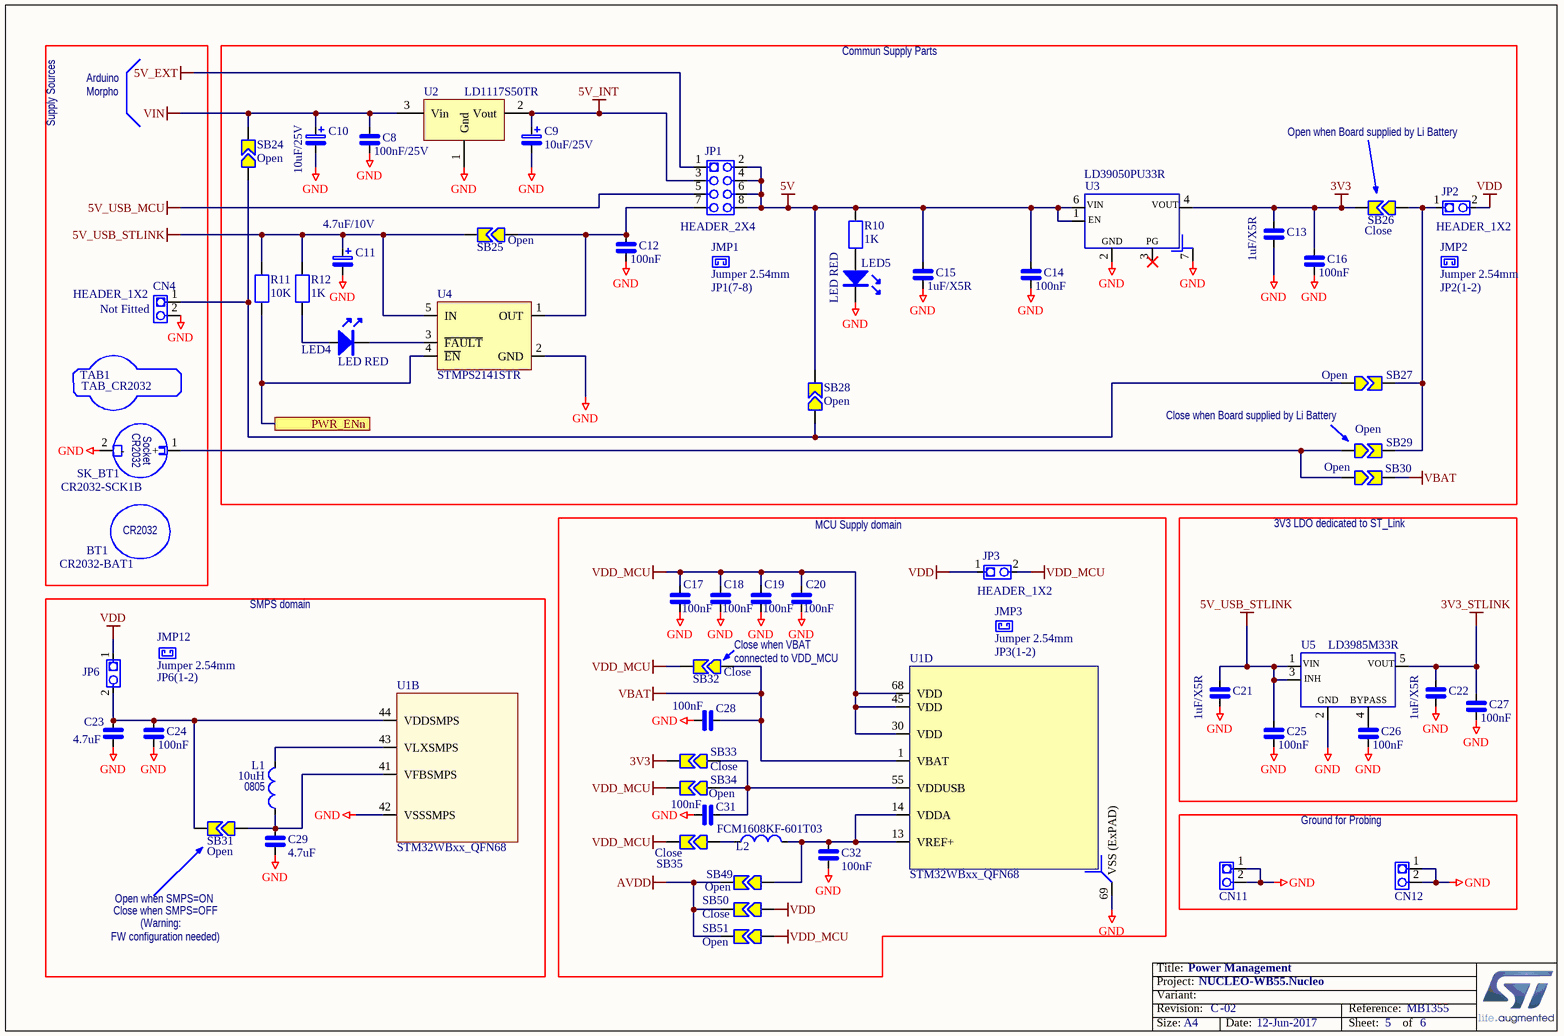
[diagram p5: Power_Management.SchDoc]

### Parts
BT1  CR2032-BAT1  [CR2032_BAT]
C8  100nF/25V  [0402_CAP_NPOL]
C9  10uF/25V  [1210_CAP_POL]
C10  10uF/25V  [1210_CAP_POL]
C11  4.7uF/10V  [1210_CAP_POL]
C12  100nF  [0402_CAP_NPOL]
C13  1uF/X5R  [0603_CAP_NPOL]
C14  100nF  [0402_CAP_NPOL]
C15  1uF/X5R  [0603_CAP_NPOL]
C16  100nF  [0402_CAP_NPOL]
C17  100nF  [0402_CAP_NPOL]
C18  100nF  [0402_CAP_NPOL]
C19  100nF  [0402_CAP_NPOL]
C20  100nF  [0402_CAP_NPOL]
C21  1uF/X5R  [0603_CAP_NPOL]
C22  1uF/X5R  [0603_CAP_NPOL]
C23  4.7uF  [0402_CAP_NPOL]
C24  100nF  [0402_CAP_NPOL]
C25  100nF  [0402_CAP_NPOL]
C26  100nF  [0402_CAP_NPOL]
C27  100nF  [0402_CAP_NPOL]
C28  100nF  [0402_CAP_NPOL]
C29  4.7uF  [0402_CAP_NPOL]
C31  100nF  [0402_CAP_NPOL]
C32  100nF  [0402_CAP_NPOL]
CN4  HEADER_1X2  Fitted: Not Fitted  [Header NF 1x2x2.54 TH]
CN11  HEADER_1X2  [Header M 1x2x2.54 TH V]  (value not drawn)
CN12  HEADER_1X2  [Header M 1x2x2.54 TH V]  (value not drawn)
JMP1  Jumper 2.54mm  Default: JP1(7-8)  [Jumper 2.54mm BLACK]
JMP2  Jumper 2.54mm  Default: JP2(1-2)  [Jumper 2.54mm BLACK]
JMP3  Jumper 2.54mm  default: JP3(1-2)  [Jumper 2.54mm BLACK]
JMP12  Jumper 2.54mm  default: JP6(1-2)  [Jumper 2.54mm BLACK]
JP1  HEADER_2X4  [Header M 2x4x2.54 TH V]
JP2  HEADER_1X2  [Header M 1x2x2.54 TH V]
JP3  HEADER_1X2  [Header M 1x2x2.54 TH V]
JP6  HEADER_1X2  [Header M 1x2x2.54 TH V]  (value not drawn)
L1  10uH  [0805_COIL]
L2  FCM1608KF-601T03  [0603_COIL]
LED4  LED RED  [0603_LED_RED]
LED5  LED RED  [0603_LED_RED]
R10  1K  [0402_RES]
R11  10K  [0402_RES]
R12  1K  [0402_RES]
SB24  Open  [SB-tiny]
SB25  Open  [SB-tiny]
SB26  Close  [SB-tiny]
SB27  Open  [SB-tiny]
SB28  Open  [SB-tiny]
SB29  Open  [SB-tiny]
SB30  Open  [SB-tiny]
SB31  Open  [SB-tiny]
SB32  Close  [SB-tiny]
SB33  Close  [SB-tiny]
SB34  Open  [SB-tiny]
SB35  Close  [SB-tiny]
SB49  Open  [SB-tiny]
SB50  Close  [SB-tiny]
SB51  Open  [SB-tiny]
SK_BT1  CR2032-SCK1B  [CR2032-SCK1]
TAB1  TAB_CR2032
U1  STM32WBxx_QFN68  [VFQFPN68_8x8x0.1_p0.4]  (parts B,D of 5)
U2  LD1117S50TR  [SOT223_SC73_A]
U3  LD39050PU33R  [DFN6 3x3mm]
U4  STMPS2141STR  [SOT23-5]
U5  LD3985M33R  [SOT23-5]

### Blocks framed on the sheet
3V3 LDO dedicated to ST_Link: C21 C22 C25-C27 U5
Ground for Probing: CN11 CN12

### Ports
PWR_ENn

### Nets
3V3: C13.1 C16.1 SB26.2 SB33.2 U3.4(VOUT)
3V3_STLINK: C22.1 C27.1 U5.5(VOUT)
5V: C14.1 C15.1 JP1.2 JP1.4 JP1.6 JP1.8 R10.1 SB28.2 U3.1(EN) U3.6(VIN)
5V_EXT: JP1.1
5V_INT: C9.1 JP1.3 U2.2(Vout)
5V_USB_MCU: JP1.5
5V_USB_STLINK: C11.1 C21.1 C25.1 R11.1 R12.1 SB25.2 U4.5(IN) U5.1(VIN) U5.3(CE)
AVDD: SB49.2 SB50.2 SB51.2
GND: C8.2 C9.2 C10.2 C11.2 C12.2 C13.2 C14.2 C15.2 C16.2 C17.2 C18.2 C19.2 C20.2 C21.2 C22.2 C23.2 C24.2 C25.2 C26.2 C27.2 C28.2 C29.2 C31.2 C32.2 CN4.2 CN11.1 CN11.2 CN12.1 CN12.2 LED5.K SK_BT1.2(-) U1.42(VSSSMPS) U1.69(VSS_(ExPAD)) U2.1(Gnd) U3.2(VSS) U3.7 U4.2(GND) U5.2(VSS)
VBAT: C28.1 SB30.2 SB32.1 U1.1(VBAT)
VDD: JP2.2 JP3.1 JP6.1 SB50.1
VDD_MCU: C17.1 C18.1 C19.1 C20.1 JP3.2 SB32.2 SB34.2 SB35.2 SB51.1 U1.30(VDD) U1.45(VDD) U1.68(VDD)
VIN: C8.1 C10.1 SB24.2 U2.3(Vin)
PWR_ENn: R11.2 U4.4(~{EN}) ; port PWR_ENn
NetC12_1: C12.1 JP1.7 SB25.1 U4.1(OUT)
NetC23_1: C23.1 C24.1 JP6.2 SB31.2 U1.44(VDDSMPS)
NetC26_1: C26.1 U5.4(BYPASS)
NetC29_1: C29.1 L1.1 SB31.1 U1.41(VFBSMPS)
NetC31_1: C31.1 SB33.1 SB34.1 U1.55(VDDUSB)
NetC32_1: C32.1 L2.2 SB49.1 U1.13(VREF+) U1.14(VDDA)
NetCN4_1: CN4.1 SB24.1 SB27.1 SB28.1
NetJP2_1: JP2.1 SB26.1 SB27.2 SB29.2
NetL1_2: L1.2 U1.43(VLXSMPS)
NetL2_1: L2.1 SB35.1
NetLED4_A: LED4.A R12.2
NetLED4_K: LED4.K U4.3(~{FAULT})
NetLED5_A: LED5.A R10.2
NetSB29_1: SB29.1 SB30.1 SK_BT1.1(+)

Not connected (* = marked no-connect by the designer): U3 3(PG)*

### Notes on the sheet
- Arduino
- Morpho
- Commun Supply Parts
- Supply Sources
- Open when Board supplied by Li Battery
- Close when Board supplied by Li Battery
- MCU Supply domain
- SMPS domain
- (near SB32) Close when VBAT
- (near SB32) connected to VDD_MCU
- (near L1) 0805
- Close when SMPS=OFF
- Open when SMPS=ON
- FW configuration needed)
- (Warning:

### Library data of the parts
C8 C12-C29 C31 C32 = CAP_NPOL: Capacitor_not polarized
C9-C11 = CAP_POL: Condensateur_polarise
JP2 JP3 JP6 = HEADER_1X2_L
L1 = IND_74479777310A: Coil Wurtz 10uH ref: 74479777310A
L2 = IND_FCM1608KF-601T03
LED4 LED5 = LED: Light-Emitting Diode
R10-R12 = RES: Resistor
SB24-SB35 SB49-SB51 = Strap2: Solder Jumper; Solder: YES
TAB1 = CR2032_TAB
U2 = LD1117S50TR: IC REG LDO 5V 0.8A SOT223; Manuf_1: STM; ECCN_US/EU: EAR99/NEC; Ref St: 9176133; Fitted: YES
U3 = LD39050PU33R: 3.3V voltage regulator 500mA
U4 = STMPS2141STR: Enhanced single channel power switches; Manuf_1: STM; Provided: ST; ECCN_US/EU: EAR99/NEC; Ref St: 9159003
U5 = LD3985M33R: 3.3V low drop voltage regulator; Manufacturer: STMicroelectronics; Isortie max: 550mA; V entrée max: 6V

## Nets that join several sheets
3V3: Extension_CN (CN6.2 CN6.4 CN7.12 CN7.16), Power_Management (5 pins)
3V3_STLINK: ST_LINK_V2-1 (20 pins), Power_Management (C22.1 C27.1 U5.5)
5V: Extension_CN (CN6.5 CN7.18), ST_LINK_V2-1 (D2.1), Power_Management (10 pins)
5V_EXT: Extension_CN (CN7.6), Power_Management (JP1.1)
5V_INT: Extension_CN (R33.2), Power_Management (C9.1 JP1.3 U2.2)
5V_USB_MCU: Extension_CN (CN1.1 CN10.8 U6.5), Power_Management (JP1.5)
5V_USB_STLINK: ST_LINK_V2-1 (CN15.1 R16.2 U9.5), Power_Management (9 pins)
AVDD: Extension_CN (CN5.8 CN10.7), Power_Management (SB49.2 SB50.2 SB51.2)
GND: MCU (16 pins), RF (15 pins), Extension_CN (13 pins), ST_LINK_V2-1 (35 pins), Power_Management (38 pins)
VBAT: Extension_CN (CN7.33), Power_Management (C28.1 SB30.2 SB32.1 U1.1)
VDD: RF (JP4.1), Extension_CN (CN7.5), ST_LINK_V2-1 (JP5.11), Power_Management (JP2.2 JP3.1 JP6.1 SB50.1)
VDD_MCU: MCU (R5.1), Power_Management (12 pins)
VIN: Extension_CN (CN6.8 CN7.24), Power_Management (C8.1 C10.1 SB24.2 U2.3)
BOOT0: MCU (R6.1 U1.5), Extension_CN (CN7.7)
NRST: MCU (D1.K SW4.1), Extension_CN (CN6.3 CN7.14), ST_LINK_V2-1 (JP5.3)
OSC_IN: MCU (SB43.2), Extension_CN (CN7.29)
OSC_OUT: MCU (SB44.2), Extension_CN (CN7.31)
PA0: MCU (U1.15), Extension_CN (CN7.34 CN8.4)
PA1: MCU (U1.16), Extension_CN (CN8.3 SB14.2)
PA2: MCU (U1.17), Extension_CN (CN9.2 SB15.2)
PA3: MCU (U1.18), Extension_CN (CN9.1 CN10.37)
PA4: MCU (U1.19), Extension_CN (SB5.2 SB41.1)
PA5: MCU (U1.20), Extension_CN (CN5.6 CN10.11)
PA6: MCU (U1.21), Extension_CN (CN5.5 CN10.13)
PA7: MCU (U1.22), Extension_CN (CN5.4 SB1.2)
PA8: MCU (U1.23), Extension_CN (CN9.7 CN10.25)
PA9: MCU (U1.24), Extension_CN (CN5.2 SB8.2 SB10.1)
PA10: MCU (U1.51), Extension_CN (CN9.4 SB3.2 SB11.2)
PA13: MCU (U1.54), Extension_CN (CN7.13), ST_LINK_V2-1 (JP5.5)
PA14: MCU (U1.56), Extension_CN (CN7.15), ST_LINK_V2-1 (JP5.7)
PA15: MCU (U1.57), Extension_CN (CN9.6 CN10.27)
PB0: MCU (R3.1 SB22.1 U1.38), Extension_CN (CN10.22)
PB1: MCU (R4.1 SB23.1 U1.39), Extension_CN (CN10.24)
PB2: MCU (U1.27), Extension_CN (CN7.2)
PB3: MCU (U1.63), Extension_CN (SB13.1), ST_LINK_V2-1 (JP5.9)
PB4: MCU (U1.64), Extension_CN (CN10.4)
PB5: MCU (R2.1 U1.65), Extension_CN (SB7.1)
PB6: MCU (U1.66), Extension_CN (SB16.2 SB17.1), ST_LINK_V2-1 (JP5.13)
PB7: MCU (U1.67), Extension_CN (CN10.6), ST_LINK_V2-1 (JP5.15)
PB8: MCU (U1.6), Extension_CN (CN5.10 CN10.3)
PB9: MCU (U1.7), Extension_CN (CN5.9 CN10.5)
PB10: MCU (U1.28), Extension_CN (SB6.2 SB42.1)
PB11: MCU (U1.29), Extension_CN (CN7.1)
PB12: MCU (U1.46), Extension_CN (CN10.16)
PB13: MCU (U1.47), Extension_CN (SB12.1)
PB14: MCU (U1.48), Extension_CN (CN10.28)
PB15: MCU (U1.49), Extension_CN (SB9.1)
PC0: MCU (U1.9), Extension_CN (CN7.28 CN8.1)
PC1: MCU (U1.10), Extension_CN (CN7.30 CN8.2)
PC2: MCU (U1.11), Extension_CN (CN7.38 CN8.6)
PC3: MCU (U1.12), Extension_CN (CN7.36 CN8.5)
PC4: MCU (SB47.2 U1.25), Extension_CN (CN10.1)
PC5: MCU (U1.26), Extension_CN (CN7.3)
PC6: MCU (U1.50), Extension_CN (CN9.3 CN10.33)
PC10: MCU (U1.58), Extension_CN (CN9.5 CN10.29)
PC11: MCU (U1.59), Extension_CN (SB18.2)
PC12: MCU (U1.60), Extension_CN (CN5.1 CN10.21)
PC13: MCU (SB48.2 U1.2), Extension_CN (CN9.8 CN10.23)
PC14: MCU (SB45.2), Extension_CN (CN7.25)
PC15: MCU (SB46.2), Extension_CN (CN7.27)
PD0: MCU (R8.2 U1.61), Extension_CN (CN10.36)
PD1: MCU (R9.2 U1.62), Extension_CN (CN10.38)
PE4: MCU (U1.40), Extension_CN (CN7.4)
PWR_ENn: ST_LINK_V2-1 (U8.28), Power_Management (R11.2 U4.4)
USB_N: MCU (U1.52), Extension_CN (SB4.1 U6.1)
USB_P: MCU (U1.53), Extension_CN (SB2.1 U6.3)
